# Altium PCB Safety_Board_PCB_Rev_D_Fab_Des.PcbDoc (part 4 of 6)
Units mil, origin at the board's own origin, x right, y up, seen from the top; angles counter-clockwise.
Board outline 11000 x 4400 mil, 6 copper layers (L1-TOP, L2-Plane, L3-Signal, L4-Signal, L5-Plane, L6-BOT); 712 components, 540 nets, 2214 pads, 875 vias.
Unrouted connection lines stored in the file: 3.
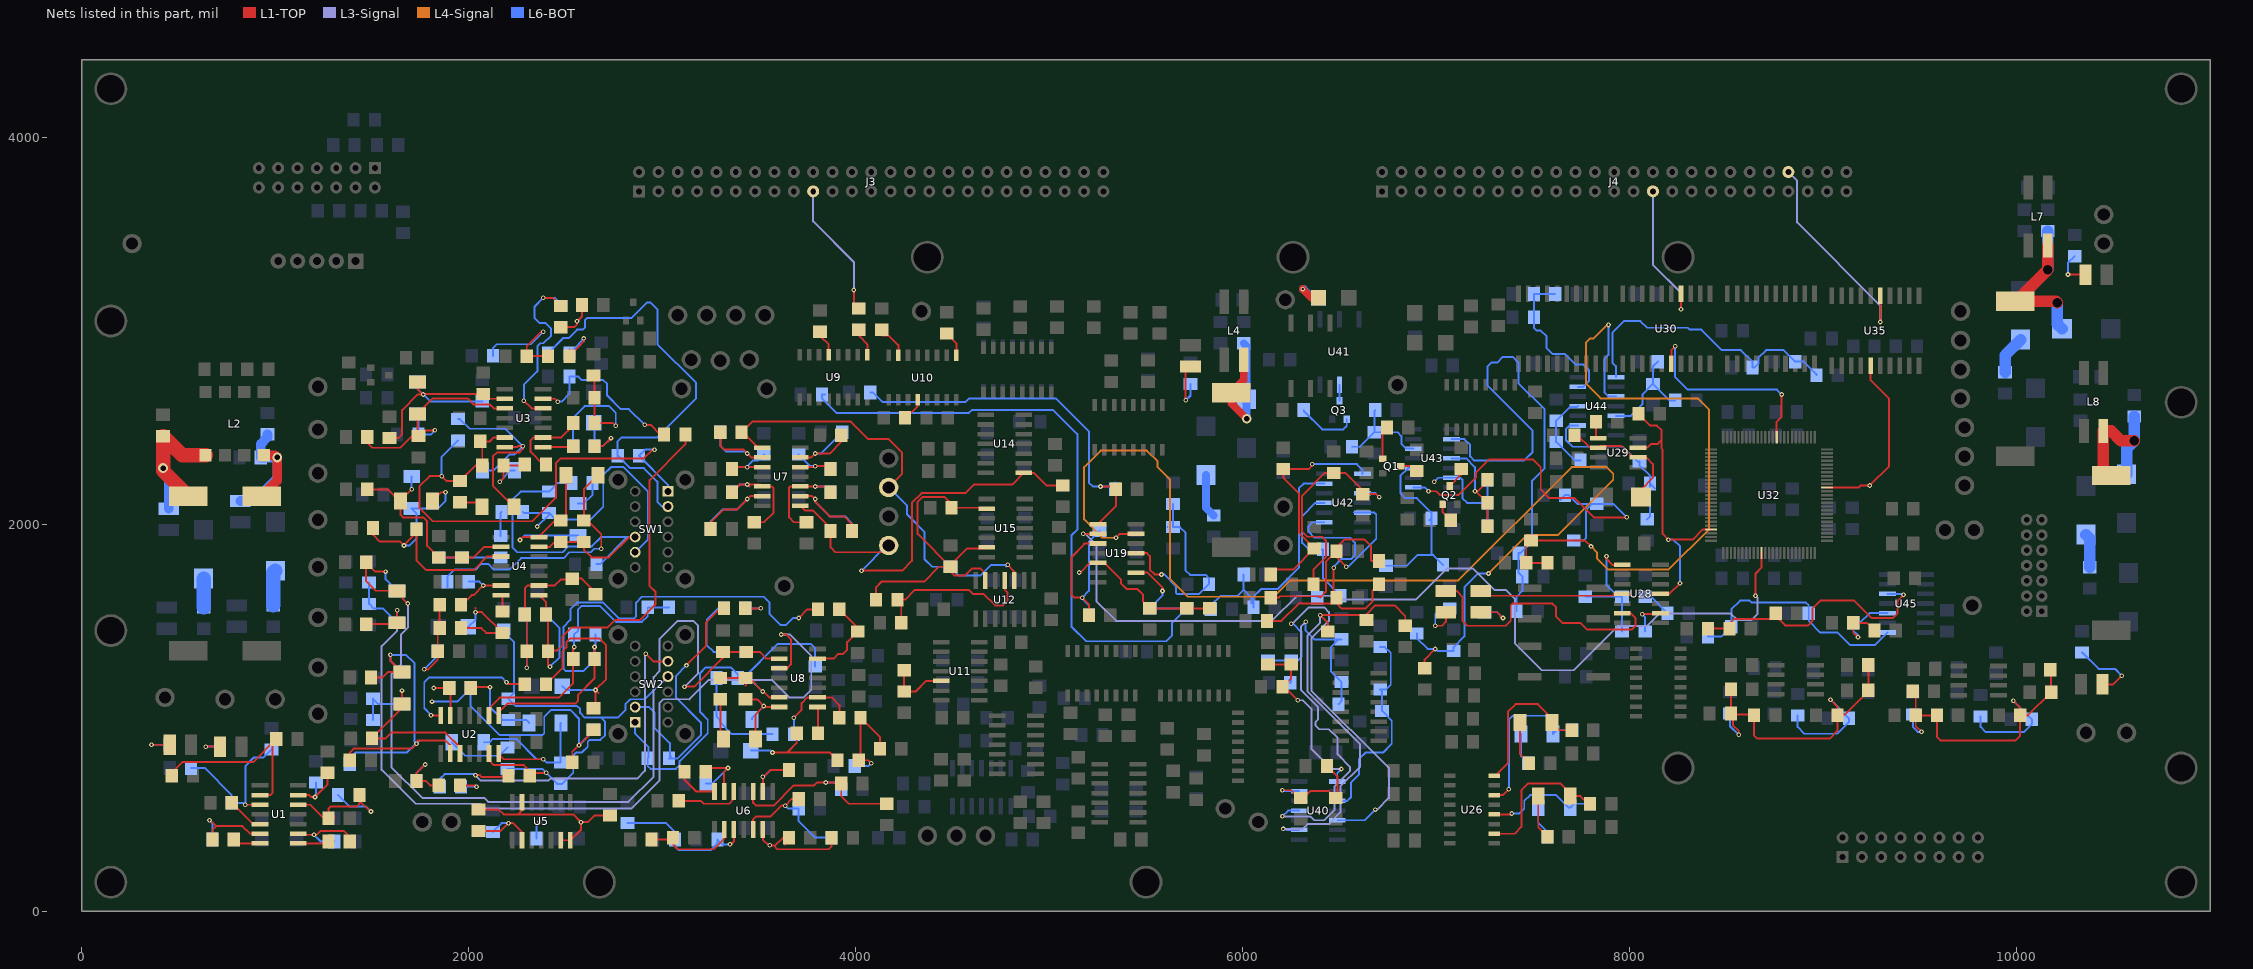
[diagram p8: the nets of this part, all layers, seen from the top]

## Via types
v1: diameter 24, hole 12, L1-TOP to L6-BOT, 720 vias
v2: diameter 50, hole 28, L1-TOP to L6-BOT, 138 vias
v3: diameter 28, hole 50, L1-TOP to L6-BOT, 17 vias

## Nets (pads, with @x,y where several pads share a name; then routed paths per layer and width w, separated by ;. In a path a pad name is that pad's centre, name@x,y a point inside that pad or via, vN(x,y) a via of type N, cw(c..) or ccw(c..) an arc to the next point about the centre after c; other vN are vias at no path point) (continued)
IBS: R53.2 R269.1 TP26.1 U7.1 U12.10 | length 2350.5
  L1-TOP w10: U7.1@3516.57,2395 3495,2395 3415,2475 R53.2@3410.12,2475 3465.12,2530 3975,2530 4065,2440 4170,2440 4240,2370 4240,2260 TP26.1@4170,2190 TP26.1@4205,2190 ; v1(4785,1790) 4820,1755 U12.10@4820,1708.43
  L6-BOT w10: TP26.1@4170,2190 4265,2095 4265,2050 4355,1960 4355,1820 4395.12,1779.88 R269.1@4490,1779.88 4490.12,1780 4490.12,1774.88 4530,1735 4645,1735 4700,1790 v1(4785,1790) 4775,1780
IBW: R69.2 R104.1 TP28.1 U7.8 U14.8 | length 2280.6
  L1-TOP w10: U7.8@3713.43,2095 3738.43,2070 3780,2070 3860,1990 R69.2@3860,1970 ; R69.2@3869.88,1965 3869.88,1880.12 3895,1855 4135,1855 TP28.1@4170,1890 TP28.1@4155,1890 ; v1(4030,1760) 4240,1760 4290,1810 4290,2110 4340,2160 4565,2160 4610,2205 4808.43,2205 U14.8@4868.43,2265 4920,2265 4984.88,2200.12 R104.1@5070,2200.12
  L6-BOT w10: v1(4030,1760) 4160,1890 TP28.1@4170,1890
"LAB SELECT LATCH": J4.44 U35.15 | length 1107.9
  L1-TOP w10: v1(9295,3045) U35.15@9295,3181.1
  L3-Signal w10: J4.44@8820,3820 8865,3775 8865,3560 9295,3130 v1(9295,3045)
LAB_SELECT_LATCH: U32.65 U35.5 | length 924.9
  L1-TOP w10: U32.65@9019.21,2189.37 9184.37,2189.37 9195,2200 v1(9240,2200) 9340,2300 9340,2649.04 9245,2744.04 U35.5@9245,2818.9
LOCAL_CLOCK: R169.2 U28.11 U29.3 U32.22 | length 1505.6
  L1-TOP w10: U29.3@8042.32,2395.04 8090.04,2395.04 8110,2415 8145,2415 8165,2435 ; R169.2@8044.88,2570 8105,2509.88 8140.12,2509.88 8165,2485 8165,2390 8170,2385 8170,1950 v1(8200,1920) 8325,1920 8377.83,1972.83 U32.22@8420.79,1972.83 ; U28.11@8158.43,1640 8205,1640 v1(8260,1695)
  L6-BOT w10: v1(8200,1920) 8225,1920 8260,1885 v1(8260,1695)
"MTR CNTR ERR": J3.19 R73.1 | length 702.2
  L1-TOP w10: v1(3990,3210) 3990,3140.12 R73.1@4015,3115.12
  L3-Signal w10: J3.19@3780,3720 3780,3565 3990,3355 v1(3990,3210)
"MTR CNTR ERR LATCH": J4.29 U30.14 | length 751.2
  L1-TOP w10: v1(8265,3110) U30.14@8265,3191.1
  L3-Signal w10: J4.29@8120,3720 8120,3340 8265,3195 v1(8265,3110)
MTR_CNTR_ERR_BUF: U19.2 U32.36 | length 4880.2
  L1-TOP w10: v1(5175,1950) U19.2@5251.57,1950 ; v1(8650,1630) 8650,1745 8680.63,1775.63 U32.36@8680.63,1850.79
  L3-Signal w10: v1(5175,1950) 5185,1950 5245,1890 5245,1600 5345,1500 6150.96,1500 6280.96,1630 6455,1630 6475,1610 6895,1610 7057,1772 7188,1772 7300,1660 7360,1660 7406,1614 7406,1384 7545,1245 7710,1245 7938,1473 8088,1473 8153,1538 8522,1538 8555,1505 8630,1505 8660,1535 8660,1620 v1(8650,1630)
MTR_CNTR_ERR_LATCH: U30.6 U32.86 | length 1078.1
  L1-TOP w10: U30.6@8215,2828.9 8215,2900 v1(8235,2920) ; U32.86@8759.37,2449.21 8759.37,2529.37 8785,2555 v1(8785,2670)
  L6-BOT w10: v1(8235,2920) 8235,2760 8300,2695 8760,2695 v1(8785,2670)
NetC4_2: C4.2 D5.A D18.K R15.2 R207.2 U2.2 | length 2090
  L1-TOP w10: C4.2@1361.89,753.11 C4.2@1389.53,753.11 ; C4.2@1384.88,780 1384.88,819.88 1405,840 1705,840 v1(1730,865) ; R15.2@1494.76,1208.11 1554.65,1208.11 1582.32,1235.79 D5.A@1662.32,1235.79 ; v1(1595,1325) 1595,1295.43 D5.A@1654.65,1235.79 ; v1@1734.65,874.65 1734.65,883.11 1879.65,883.11 1904.65,858.11 U2.2@1904.65,784.69
  L6-BOT w10: R207.2@1384.88,760 1384.88,789.88 1415,820 1680,820 1725,865 v1(1730,865) ; D18.K@1654.65,1235.79 1595,1295.43 v1(1595,1325) 1675,1325 1720,1280 1720,875 v1(1730,865) ; 1744.65,879.65 v1(1730,865)
NetC5_2: C5.2 R7.2 R208.2 U1.12 | length 784.1
  L1-TOP w10: U1.12@1118.43,550 1180,550 1250,480 R7.2@1274.88,480 1275,480.12 1275,530 1285,540 1420,540 1435.12,555.12 C5.2@1435.12,600 C5.2@1415.12,580 ; R7.2@1304.88,480 R7.2@1304.88,489.88 ; C5.2@1435.12,569.88 1495,510 v1(1495,515)
  L6-BOT w10: R208.2@1324.88,600 1384.88,540 1470,540 v1(1495,515)
NetC6_2: C6.2 D4.K D16.A R10.2 R204.2 U3.3 | length 1262.1
  L1-TOP w10: R10.2@1475.12,2450 1475.12,2419.88 1500,2395 1645,2395 1705.12,2455.12 C6.2@1740,2455.12 ; C6.2@1734.65,2468.23 C6.2@1739.76,2463.11 ; v1(1825,2485) 1769.88,2485 C6.2@1740,2455.12 ; U3.3@2186.22,2598.11 2129.65,2598.11 2109.65,2618.11 2026.89,2618.11 1995,2650 1814.21,2650 D4.K@1734.65,2570.43 1734.65,2460.47 C6.2@1740,2455.12
  L6-BOT w10: D16.A@1734.65,2570.43 1739.76,2565.32 R204.2@1739.76,2463.11 1803.11,2463.11 v1(1825,2485)
NetC7_2: C7.2 D2.K D17.A R12.2 R205.1 U4.3 | length 1523.5
  L1-TOP w10: R12.2@1505.12,1980 1505.12,1944.88 1540,1910 1645,1910 v1(1665,1890) C7.2@1729.76,1954.76 ; C7.2@1729.76,1973.11 1729.76,1812.99 1779.65,1763.11 2024.65,1763.11 2094.65,1833.11 U4.3@2166.22,1833.11 ; D2.K@1812.68,2120 1857.68,2165 v1(1880,2165)
  L6-BOT w10: v1(1665,1890) 1695,1890 1729.76,1924.76 1729.76,2055.32 D17.A@1704.65,2080.43 1840.43,2080.43 1880,2120 v1(1880,2165)
NetC8_2: C8.2 R25.1 R212.2 | length 374.3
  L1-TOP w10: C8.2@1759.76,643.11 C8.2@1729.76,673.11 ; v1(1774.65,758.11) 1729.76,713.23 C8.2@1729.76,673.11 ; R25.1@1844.88,650 1800,650 1776.89,673.11 C8.2@1729.76,673.11
  L6-BOT w10: R212.2@1729.76,673.11 1729.76,713.23 v1(1774.65,758.11)
NetC9_2: C9.2 D2.A D17.K R11.2 R26.2 U4.2 | length 1124.4
  L1-TOP w10: R11.2@1475.12,2180 1580,2180 D2.A@1643.66,2116.34 ; v1(1705,2180) 1647.32,2122.32 1647.32,2047.68 1660,2035 1765,2035 1784.65,2015.35 1784.65,1887.99 C9.2@1844.65,1827.99 R26.2@1964.65,1827.99 1964.76,1828.11 2024.65,1828.11 2079.65,1883.11 U4.2@2166.22,1883.11
  L6-BOT w10: D17.K@1704.65,2245.79 1705,2245.43 v1(1705,2180)
NetC11_2: C11.2 D4.A D16.K R9.2 R219.2 U3.2 | length 1250.5
  L1-TOP w10: R9.2@1590,2444.88 1634.88,2444.88 1655,2465 1655,2590 1734.65,2669.65 1764.65,2669.65 1767.99,2672.99 C11.2@2074.65,2672.99 2099.53,2648.11 U3.2@2186.22,2648.11 ; D4.A@1734.65,2735.79 1734.65,2700.35 v1(1765,2670)
  L6-BOT w10: D16.K@1734.65,2735.79 1734.65,2700.35 1800.12,2634.88 R219.2@2070,2634.88
NetC13_2: C13.2 R34.1 R218.2 | length 613
  L1-TOP w10: v1(2385,2995) 2375,2995 2299.76,2919.76 C13.2@2299.76,2868.11 R34.1@2409.53,2868.11
  L6-BOT w10: R218.2@2125.12,2870 2125.12,2910.12 2145,2930 2320,2930 v1(2385,2995)
NetC14_1: C14.1 C70.1 R31.1 R37.2 R44.1 U4.9 | length 1123.5
  L1-TOP w10: v1(2299.65,1258.11) 2299.53,1258.23 2299.53,1523.11 R31.1@2289.53,1533.11 2289.53,1667.99 2304.65,1683.11 2444.65,1683.11 2474.65,1713.11 2529.53,1713.11 R37.2@2534.65,1718.23 2584.53,1718.23 2654.65,1648.11 R44.1@2654.65,1637.99
  L6-BOT w10: C70.1@2289.53,1527.99 C70.1@2289.53,1533.11 2299.65,1522.99 v1(2299.65,1258.11)
NetC14_2: C14.2 C70.2 R31.2 R48.1 U4.8 | length 2355.2
  L1-TOP w10: U4.8@2363.07,1633.11 2399.76,1596.42 R31.2@2399.76,1533.11 2409.76,1523.11 2409.76,1272.99 v1(2419.65,1263.11) ; C14.2@2414.76,1348.11 2458.11,1348.11 2485,1375 2485,1420 2530,1465 2716.54,1465 2756.54,1505 2885,1505 2965,1585 2965,1650 2934.65,1680.35 2934.65,2228.11 3119.76,2413.23 R48.1@3119.76,2463.11
  L6-BOT w10: C70.2@2399.76,1533.11 2469.65,1463.23 2469.65,1313.11 v1(2419.65,1263.11)
NetC17_1: C17.1 R41.1 R228.2 R230.1 R232.1 SW1.10 U4.13 | length 2060.1
  L1-TOP w10: U4.13@2363.07,1883.11 2419.65,1883.11 C17.1@2444.53,1907.99 ; C17.1@2474.65,1907.99 R41.1@2594.65,1907.99 2594.65,1868.11 2634.65,1828.11 2724.65,1828.11 2830.28,1933.74 SW1.10@2860,1933.74
  L6-BOT w10: R232.1@2529.53,2213.11 2459.53,2213.11 R228.2@2414.65,2168.23 2268.23,2168.23 2225,2125 2225,1880 2250,1855 2485,1855 2515,1885 2635.96,1885 2684.7,1933.74 SW1.10@2860,1933.74 ; R230.1@2659.76,1793.11 2679.65,1793.11 2820.28,1933.74
NetC17_2: C17.2 D7.K D25.A U4.14 | length 808.9
  L1-TOP w10: v1(2264.65,1918.11) 2279.65,1933.11 U4.14@2363.07,1933.11 2363.07,1936.54 2444.76,2018.23 C17.2@2474.65,2018.23 2501.97,2045.55 D7.K@2501.97,2253.11
  L6-BOT w10: v1(2264.65,1918.11) 2286.97,1940.43 D25.A@2564.65,1940.43
NetC18_1: C18.1 C72.1 R233.1 R236.2 R240.1 U2.9 | length 1551.1
  L1-TOP w10: U2.9@2104.65,1011.54 2104.65,1048.11 2159.65,1103.11 2464.65,1103.11 2539.53,1177.99 2539.53,1359.53 v1(2545,1365)
  L6-BOT w10: R233.1@2539.53,1303.11 2539.53,1359.53 v1(2545,1365) 2544.88,1365.12 C72.1@2544.88,1430 2565,1450.12 2565,1560 2583,1578 2677,1578 2760,1495 2895,1495 2925.12,1525.12 R236.2@2925.12,1570 R240.1@3034.88,1570
NetC18_2: C18.2 C72.2 R66.1 R233.2 U2.8 | length 2948.9
  L1-TOP w10: U2.8@2154.65,1011.54 2154.65,1028.11 2199.65,1073.11 2549.65,1073.11 2564.65,1088.11 2564.65,1118.11 2649.76,1203.23 C18.2@2649.76,1303.11 2650,1303.35 v1(2650,1365) ; v1(3705,1515) 3750,1560 R66.1@3804.88,1560
  L6-BOT w10: R233.2@2649.76,1298.59 2593.08,1241.92 2500,1241.92 2488.46,1253.46 2488.46,1468.46 2525,1505 2525,1560 2560,1595 2695,1595 2778,1512 2852,1512 2865,1525 2865,1595 2895,1625 3525,1625 3555,1595 3555,1535 3610,1480 3640,1480 3675,1515 v1(3705,1515) ; R233.2@2649.76,1303.11 2649.76,1364.76 2655.12,1370.12 C72.2@2655.12,1430
NetC20_1: C20.1 R245.2 | length 159.8
  L1-TOP w10: C20.1@3428.54,1565 v1(3508.43,1565)
  L6-BOT w10: R245.2@3428.54,1565 v1(3508.43,1565)
NetC20_2: C20.2 R238.1 SW2.2 | length 1428.6
  L1-TOP w10: v1(3125,1270) 3225,1370 3225,1490 3300,1565 C20.2@3318.31,1565
  L6-BOT w10: SW2.2@2860,1055 2932.76,1055 2959.65,1028.11 2959.65,948.11 3039.76,867.99 R238.1@3039.76,794.65 ; R238.1@3045.12,800 R238.1@3035.12,790 3080,790 3200,910 3200,975 3070,1105 3070,1215 v1(3125,1270)
NetC21_1: C21.1 R52.1 R238.2 R242.1 R256.2 SW2.1 U8.6 | length 2284.8
  L1-TOP w10: R52.1@3300,1205.12 C21.1@3430,1205.12 3449.88,1205.12 v1(3520,1135) ; 3430,1165.12 3435,1170.12 ; v1@3523.43,1135 3553.43,1105 U8.6@3605,1105
  L6-BOT w10: SW2.1@2860,976.26 2860,917.76 2929.53,848.23 2929.53,794.65 R238.2@2924.88,790 2924.88,750.12 2940,735 3070,735 3090,755 3090,775 3235,920 3235,990 3195,1030 3195,1230 3225,1260 3355,1260 3390.12,1224.88 R242.1@3390.12,1205 3450,1205 v1(3520,1135) ; R242.1@3420,1205 3595,1380 3770,1380 3790,1360 R256.2@3790,1265.12
NetC21_2: C21.2 D9.K D27.A U8.7 | length 481.8
  L1-TOP w10: C21.2@3430,1094.88 3490.12,1094.88 3530,1055 U8.7@3605,1055 U8.7@3600.12,1059.88 ; D9.K@3482.68,890 3482.68,1017.68 v1(3525,1060)
  L6-BOT w10: D27.A@3462.68,990 3462.68,997.68 v1(3525,1060)
NetC22_2: C22.2 D3.A D15.K R13.2 R57.1 U8.2 | length 4888.4
  L1-TOP w10: v1(1570,1755) 1517.87,1755 R13.2@1469.76,1803.11 1469.76,1705.24 1519.21,1655.79 D3.A@1629.65,1655.79 1629.65,1645.35 v1(1685,1590) ; v1(3115,1160) 3165,1160 3313.43,1308.43 R57.1@3313.43,1339.88 3503.54,1339.88 3538.43,1305 U8.2@3605,1305
  L3-Signal w10: v1(1685,1590) 1685,1465 1650,1430 1650,1275 1600,1225 1600,745 1760,585 2080,585 2100,565 2825,565 2955,695 2955,1210 2985,1240 2985,1405 3080,1500 3160,1500 3185,1475 3185,1230 v1(3115,1160)
  L6-BOT w10: v1(1570,1755) 1570,1715 1629.21,1655.79 D15.K@1629.65,1655.79
NetC25_2: C25.2 R117.1 R123.1 U19.5 | length 825.2
  L1-TOP w10: v1(5155,1750) 5160,1750 5210,1800 5285,1800 5370,1715 5370,1695 5400,1665 5455,1665 5485,1635 5485,1600.12 R117.1@5520,1565.12 C25.2@5710,1565.12 R123.1@5830,1565.12
NetC26_2: C26.2 R127.1 R132.1 U40.1 | length 935.5
  L1-TOP w10: C26.2@6130,1274.88 R132.1@6250,1274.88 6250,1204.88 R127.1@6205.12,1160 6215,1160 v1(6285,1090) ; R132.1@6245,1289.88 R132.1@6250,1294.88
  L3-Signal w10: v1(6285,1090) 6310,1090 6355,1045 6355,840 6460,735 v1(6510,735)
  L6-BOT w10: U40.1@6488.43,670 6488.43,713.43 v1(6510,735)
NetC27_2: C27.2 R125.1 R129.1 U42.1 | length 1212.1
  L1-TOP w10: R125.1@6145.12,1740 6170.12,1765 6260.12,1765 C27.2@6370,1874.88 6320,1924.88 6320,1925 6290,1955 6290,2160 6210,2240 R129.1@6210,2284.88 6339.88,2284.88 6360,2305 v1(6360,2310)
  L6-BOT w10: v1(6360,2310) 6590,2310 6618.43,2281.57 U42.1@6618.43,2260
NetC28_2: C28.2 R130.1 R133.1 U40.13 | length 597.8
  L1-TOP w10: v1(6205,625) 6250,625 R130.1@6289.88,585.12 ; R130.1@6300,585.12 6315.12,585.12 6350,620 6445.12,620 R133.1@6480,585.12 6490,595.12 6490,695.12 C28.2@6435.12,750
  L6-BOT w10: v1(6205,625) 6205,630 6215,620 U40.13@6291.57,620
NetC29_2: C29.2 R131.1 R134.1 U42.3 | length 1184.4
  L1-TOP w10: R131.1@6365.12,1690 6365.12,1764.28 6430,1829.16 6430,1915 6410,1935 6334.04,1935 6307,1962.04 6307,2147 6424.88,2264.88 6530.12,2264.88 6620,2175 C29.2@6620,2155.12 6689.88,2155.12 v1(6705,2140)
  L6-BOT w10: U42.3@6618.43,2160 6685,2160 v1(6705,2140)
NetC30_2: C30.2 R126.1 R135.1 U42.5 | length 1446.8
  L1-TOP w10: R126.1@6145.12,1620 6185,1620 6192.66,1627.65 6407.66,1627.65 ; 6400,1620 6430,1650 6430,1805.12 R135.1@6484.88,1860 ; v1(6535,1780) 6484.88,1830.12 6484.88,1879.88 6525,1920 6630,1920 6662.43,1887.57 6662.43,1812.57 6665,1810 C30.2@6704.88,1810
  L6-BOT w10: v1(6535,1780) 6545,1780 6690,1925 6690,2050 6680,2060 6575,2060
NetC31_2: C31.2 R124.1 R136.1 U42.9 | length 1528.8
  L1-TOP w10: R124.1@6125.12,1500 6200,1500 6290,1590 6454.88,1590 R136.1@6484.88,1620 6470,1634.88 v1(6470,1775) ; R136.1@6470,1595 6485,1610 R136.1@6485,1645 ; R136.1@6484.88,1590.12 6510,1565 6635,1565 6670,1600 6670,1655.12 C31.2@6704.88,1690
  L6-BOT w10: U42.9@6421.57,2010 6360,2010 6340,1990 6340,1960 6370,1930 6555,1930 6580,1905 6580,1840 6560,1820 6510,1820 6470,1780 v1(6470,1775)
NetC32_2: C32.2 R137.1 R143.1 U40.9 | length 2301.1
  L1-TOP w10: R137.1@6440,1445.12 6440,1490 v1(6400,1530) 6615.12,1530 R143.1@6640,1505.12 6640,1535 6685,1580 6785,1580 6840,1525 C32.2@6840,1475.12
  L3-Signal w10: v1(6210,425) 6310,425 6335,450 6445,450 6505,510 6505,645 6605,745 6605,865 6335,1135 6335,1425 6400,1490 v1(6400,1530)
  L6-BOT w10: v1(6210,425) 6210,435 6225,420 U40.9@6291.57,420
NetC34_2: C34.2 R157.2 R158.1 U43.11 | length 555.6
  L1-TOP w10: v1(7200,2170) 7204.88,2170 C34.2@7264.88,2110 R158.1@7264.88,1990 ; 7215,2170 7264.88,2219.88 R157.2@7264.88,2230
  L6-BOT w10: U43.11@7078.43,2340 7155,2340 7200,2295 v1(7200,2170)
NetC35_2: C35.2 R156.1 R164.1 U44.3 | length 3423.3
  L1-TOP w10: R164.1@7574.88,1800 R156.1@7465.12,1800 7465.12,1890 C35.2@7490,1914.88 7770.12,1914.88 v1(7800,1885)
  L4-Signal w10: v1(7800,1885) 7830,1855 7830,1825 7890,1765 8200,1765 8410,1975 8410,2590.96 8350.96,2650 7850,2650 7775,2725 7775,2940 7795,2960 7813,2960 v1@7883,3030
  L3-Signal w10: v1@7890,3020 v1(7890,3030)
  L6-BOT w10: v1(7890,3030) 7890,2875 7870,2855 7870,2680 7890,2660 U44.3@7928.43,2660
NetC37_2: C37.2 U29.5 | length 93.4
  L1-TOP w10: C37.2@7824.88,2530 7824.88,2457.76 U29.5@7837.6,2445.04 U29.5@7839.84,2447.28
NetC38_1: C38.1 R162.1 U29.2 U29.6 | length 663
  L1-TOP w10: R162.1@7729.96,2460.04 7794.96,2395.04 U29.6@7837.6,2395.04 ; U29.6@7832.6,2390.04 7847.6,2405.04 7954.96,2405.04 8014.96,2345.04 8084.96,2345.04 8120,2310 8120,2240 8058.43,2178.43 C38.1@8058.43,2140
NetC40_2: C40.2 R170.1 R174.1 U45.5 | length 1404.1
  L1-TOP w10: C40.2@8405.12,1460 R170.1@8514.88,1460 8514.88,1484.88 8540,1510 8724.88,1510 R174.1@8754.88,1540 8754.88,1525.12 8803,1477 8922,1477 8945,1500 8945,1565 8985,1605 9160,1605 9250,1515 9360,1515 9385,1540 9385,1605 v1(9415,1635) v1@9415,1625
  L6-BOT w10: U45.5@9331.57,1640 9410,1640 v1(9415,1635)
NetC41_2: C41.2 C153.2 R171.2 R173.2 R175.2 R177.2 R178.2 R364.2 R369.1 | length 2065.8
  L1-TOP w10: R171.2@8522.85,1146.92 8522.85,1027.15 C41.2@8533.08,1016.92 ; v1(8562.96,911.92) 8562.96,931.92 8533.08,961.8 C41.2@8533.08,1016.92 ; v1(9037.96,1091.92) 9073.08,1056.8 9073.08,932.04 9032.96,891.92 8657.96,891.92 8642.85,907.04 8642.85,1016.92 C41.2@8533.08,1016.92 ; R175.2@9073.08,1016.92 9113.08,1016.92 9233.08,1136.92 R177.2@9233.08,1246.92
  L6-BOT w10: R364.2@8517.96,1021.8 8517.96,956.92 v1(8562.96,911.92) ; R369.1@8867.96,1011.8 8867.96,951.92 8902.96,916.92 9072.96,916.92 9133.08,977.04 C153.2@9133.08,996.92 9132.96,996.92 v1(9037.96,1091.92)
NetC42_2: C42.2 R176.1 R372.1 U45.3 | length 494.1
  L1-TOP w10: v1(9180,1415) 9155.12,1439.88 R176.1@9155.12,1490 9224.88,1490 C42.2@9264.88,1450
  L6-BOT w10: v1(9180,1415) 9180,1425 9155.12,1449.88 R372.1@9155.12,1490 9190,1490 9240,1540 U45.3@9331.57,1540
NetC43_2: C43.2 C160.2 R182.2 R184.2 R185.2 R186.2 R187.2 R378.2 R380.1 | length 2045.1
  L1-TOP w10: R182.2@9462.85,1136.92 9478.08,1121.68 9478.08,956.8 v1(9507.96,926.92) ; C43.2@9478.08,1011.92 R184.2@9587.85,1011.92 9587.85,902.04 9607.96,881.92 9992.96,881.92 10018.08,907.04 10018.08,1051.8 v1(9982.96,1086.92) ; R185.2@10018.08,1011.92 10058.08,1011.92 R187.2@10178.08,1131.92 10178.08,1241.92 R186.2@10173.08,1246.92
  L6-BOT w10: R378.2@9462.96,1016.8 9462.96,951.92 9487.96,926.92 v1(9507.96,926.92) ; R380.1@9812.96,1006.8 9812.96,951.92 9837.96,926.92 10037.96,926.92 10078.08,967.04 C160.2@10078.08,991.92 10077.96,991.92 v1(9982.96,1086.92)
NetC44_2: C44.2 L1.1 L2.1 R1.2 | length 846.7
  L1-TOP w75: L1.1@550,2145 420,2275 R1.2@420,2454.88 518.27,2356.61 L2.1@640,2356.61
  L6-BOT w50: v2(420,2290) 420,2275 450,2245 C44.2@450,2080.12
NetC46_2: C46.2 R190.1 | length 148.9
  L6-BOT w75: R190.1@630,1570.12 C46.2@630,1719.02
NetC47_2: C47.2 R189.2 R196.2 U1.3 | length 828.8
  L1-TOP w10: v1(845,550) U1.3@921.57,550
  L6-BOT w10: R189.2@565.12,740 635,740 775.12,599.88 C47.2@775.12,560 835,560 v1(845,550) 845,750 890,795 940.12,795 R196.2@980,834.88 R196.2@979.88,834.88
NetC48_2: C48.2 L2.4 L3.1 R193.2 R194.2 | length 888.9
  L1-TOP w50: L3.1@930,2145 1010,2225 v2(1010,2345) 998.39,2356.61 L2.4@940,2356.61
  L1-TOP w60: L3.1@930,2145 L3.1@940,2155
  L6-BOT w50: C48.2@820,2120.12 895.12,2120.12 1010,2235 v2(1010,2345) R193.2@925.12,2345 925.12,2415.12 960,2450 R194.2@960,2464.88
NetC50_1: C50.1 R195.1 | length 183
  L6-BOT w75: R195.1@990,1580.12 990,1749.02 C50.1@1000,1759.02
NetC61_2: C61.2 D3.K D15.A R14.2 R206.2 U8.3 | length 4962.2
  L1-TOP w10: R14.2@1469.76,1483.11 1622.32,1483.11 D3.K@1629.65,1490.43 1629.65,1554.65 v1(1630,1555) ; U8.3@3605,1255 3645,1255 3665,1275 3665,1405 3640,1430 v1(3615,1430)
  L3-Signal w7: 3005,1095 3140,1095
  L3-Signal w10: v1(1630,1555) 1630,1450 1550,1370 1550,730 1725,555 2060,555 2085,530 2840,530 2985,675 2985,1075 3005,1095 ; 3140,1095 3240,1195 3565,1195 3655,1105 3730,1105 3770,1145 3770,1320 3660,1430 v1(3615,1430)
  L6-BOT w10: R206.2@1484.65,1697.99 C61.2@1484.65,1588.23 1509.76,1563.11 1556.97,1563.11 D15.A@1629.65,1490.43 ; D15.A@1629.65,1474.65 D15.A@1629.65,1490.43 ; v1(1630,1555) 1630,1490.79 D15.A@1629.65,1490.43
NetC62_2: C62.2 D5.K D18.A R16.2 R209.1 U2.3 | length 1213.9
  L1-TOP w10: v1(1655,1140) 1654.65,1139.65 1654.65,1047.99 R16.2@1499.76,893.11 1569.65,893.11 1599.65,923.11 1879.65,923.11 1954.65,848.11 U2.3@1954.65,784.69
  L6-BOT w10: R209.1@1504.65,988.23 C62.2@1504.65,1097.99 1532.2,1070.43 D18.A@1654.65,1070.43 1655,1070.79 v1(1655,1140)
NetC63_1: C63.1 R25.2 | length 167.3
  L1-TOP w10: R25.2@1955.12,650 2032.76,650 v1(2039.65,643.11)
  L6-BOT w10: C63.1@1959.76,643.11 v1(2039.65,643.11)
NetC63_2: C63.2 R29.1 SW2.11 | length 2030.4
  L1-TOP w10: v1(2034.65,703.11) 2056.89,703.11 2067.59,692.41 2167.29,692.41 R29.1@2174.88,700 ; v1(2915,1330) 2953.78,1291.22 SW2.11@3029.29,1291.22
  L3-Signal w10: v1(2034.65,703.11) 2062.76,675 2411.66,675 2421.66,685 2870,685 2910,725 2910,1325 v1(2915,1330)
  L6-BOT w10: C63.2@1849.53,643.11 1849.53,682.99 1874.65,708.11 2029.65,708.11 v1(2034.65,703.11)
NetC64_1: C64.1 R19.2 R20.1 R21.1 R235.2 SW1.1 U3.6 | length 2824.6
  L1-TOP w10: U3.6@2186.22,2448.11 2129.65,2448.11 2109.65,2428.11 R19.2@2059.76,2428.11 2069.53,2418.35 R20.1@2069.53,2303.11 2034.53,2303.11 R21.1@1954.65,2223.23 1884.53,2223.23 v1(1859.65,2248.11) 1798.11,2248.11 1745,2195 1745,2085 1815,2015 2329.23,2015 2450,2135.77 2450,2315 2475,2340 2905,2340 2950,2385 v1(2960,2385)
  L6-BOT w10: v1(1859.65,2248.11) 1859.65,2347.99 C64.1@1944.65,2432.99 ; v1(2960,2385) 2911.65,2385 R235.2@2879.76,2353.11 3029.29,2203.58 SW1.1@3029.29,2169.96
NetC64_2: C64.2 D6.K D21.A U3.7 | length 1237.1
  L1-TOP w10: U3.7@2186.22,2398.11 2249.65,2398.11 2254.65,2403.11 v1(2279.65,2403.11) 2279.65,2389.65 2260,2370 2145,2370 2125,2350 2125,2197.68 D6.K@2232.68,2090
  L6-BOT w10: C64.2@1944.65,2543.23 1954.53,2543.23 2004.65,2493.11 2189.65,2493.11 v1(2279.65,2403.11) 2237.32,2360.79 2210.79,2360.79 2128.11,2278.11 D21.A@2071.97,2278.11
NetC65_1: C65.1 R222.2 | length 126.9
  L6-BOT w10: R222.2@2164.65,1938.23 2164.65,2058.23 C65.1@2169.53,2063.11
NetC65_2: C65.2 R228.1 SW1.11 | length 1357.9
  L6-BOT w10: C65.2@2279.76,2063.11 2284.88,2057.99 R228.1@2414.65,2057.99 ; v1(2354.65,1988.11) 2414.65,2048.11 R228.1@2414.65,2057.99 ; SW1.11@2860,1855 2925,1920 2925,2170 2800,2295 2735,2295 2695,2255 2695,2090 2630,2025 2447.64,2025 R228.1@2414.65,2057.99
NetC66_2: C66.2 R211.2 R222.1 | length 320
  L6-BOT w10: R211.2@1844.65,1827.99 R222.1@2164.65,1827.99
NetC69_1: C69.1 R34.2 | length 286.3
  L1-TOP w10: R34.2@2519.76,2903.23 R34.2@2519.76,2868.11 2570,2918.35 2570,2920 2595,2945 v1(2595,2960)
  L6-BOT w10: C69.1@2519.76,2903.23 C69.1@2519.76,2883.11 2570,2933.35 2570,2935 v1(2595,2960)
NetC69_2: C69.2 R235.1 SW1.2 | length 2271.7
  L6-BOT w10: C69.2@2409.53,2883.11 2489.53,2963.11 2518.11,2963.11 2560,3005 2590,3005 2600,3015 2600,3055 2610,3065 2840,3065 2920,3145 2940,3145 2975,3110 2975,2930 3175,2730 3175,2650 2973.11,2448.11 2789.65,2448.11 2769.53,2427.99 R235.1@2769.53,2338.23 ; R235.1@2769.53,2353.11 2771.89,2353.11 2835,2290 2905,2290 2975,2220 2975,2115 2998.78,2091.22 SW1.2@3029.29,2091.22
NetC73_1: C73.1 R29.2 R220.1 R223.1 R224.1 SW2.10 U2.6 | length 2563.3
  L1-TOP w10: U2.6@2104.65,814.69 2104.65,780.35 2130,755 2285,755 2315.12,724.88 R29.2@2315.12,700 2330.12,715 v1(2400,715)
  L6-BOT w7: 2835,1095 2910,1095
  L6-BOT w10: R220.1@2180,1454.88 2180,1445 2232.65,1392.35 2232.65,1126.23 R223.1@2204.65,1098.23 2242.87,1060 2560,1060 2575,1045 2575,1025 2600,1000 2770,1000 2810.85,1040.85 2810.85,1070.85 2835,1095 ; R224.1@2200,734.88 2380.12,734.88 2457.01,657.99 2482.99,657.99 2540,715 2540,805 2555,820 2585,820 2615,850 2615,875 2625,885 2680,885 2705,910 2705,980 2685,1000 ; 2910,1095 3027.48,1212.48 SW2.10@3029.29,1212.48
NetC73_2: C73.2 D20.A D23.K U2.7 | length 905.9
  L1-TOP w10: U2.7@2154.65,814.69 2154.65,810.35 2180,785 v1(2385,785)
  L6-BOT w10: D20.A@2077.32,873.11 2108.11,873.11 2125,890 2245,890 2350,785 v1(2385,785) 2401.77,768.23 C73.2@2474.65,768.23 2474.65,970.43 D23.K@2477.32,973.11
NetC78_2: C78.2 R237.2 R239.2 U6.3 | length 764.4
  L1-TOP w10: v1(3350,345) 3355,345 3370,360 U6.3@3370,421.57
  L6-BOT w10: R237.2@2820,454.88 3020.12,454.88 3065.12,409.88 3065.12,334.88 3085,315 3250,315 3285.12,350.12 C78.2@3285.12,370 3310.12,345 v1(3350,345)
NetC79_2: C79.2 R54.2 R247.2 U7.3 | length 359.4
  L1-TOP w10: R54.2@3360.12,2285 3370.12,2295 v1(3440,2295) U7.3@3516.57,2295
  L6-BOT w10: C79.2@3360.12,2285 3370.12,2295 v1(3440,2295) 3440,2300 3470,2330 3495.12,2330 R247.2@3525,2359.88
NetC80_2: C80.2 R55.2 R58.2 U7.5 | length 596
  L1-TOP w10: R55.2@3360.12,2165 3400.12,2205 3506.57,2205 U7.5@3516.57,2195 3565,2195 3575,2185 3575,2060 3525.12,2010.12 R58.2@3475,2010.12 ; v1(3440,2205) 3450,2195
  L6-BOT w10: C80.2@3360.12,2165 3400.12,2205 v1(3440,2205)
NetC82_2: C82.2 R245.1 R246.2 | length 461.1
  L6-BOT w10: R245.1@3318.31,1565 3290,1565 3230,1505 3230,1375 3265.12,1339.88 C82.2@3433.43,1339.88
NetC86_2: C86.2 R63.2 R252.2 U6.5 | length 678
  L1-TOP w10: U6.5@3470,421.57 3470,475 3485,490 3560,490 3615,545 v1(3635,545) 3670,580 R63.2@3704.88,580
  L6-BOT w10: v1(3635,545) 3650,530 C86.2@3704.88,530 3704.88,465.12 3790,380 R252.2@3874.88,380
NetC88_2: C88.2 R67.2 R248.2 U7.12 | length 360.6
  L1-TOP w10: U7.12@3713.43,2295 3785,2295 v1(3790,2300) 3850,2300 3865,2285 R67.2@3869.88,2285
  L6-BOT w10: R248.2@3705,2359.88 3764.88,2300 3854.88,2300 C88.2@3869.88,2285
NetC89_2: C89.2 R61.2 R68.2 U7.10 | length 577
  L1-TOP w10: R61.2@3745,2010.12 3679.88,2010.12 3655,2035 3655,2190 3660,2195 v1(3790,2195) 3839.88,2195 R68.2@3869.88,2165
  L6-BOT w10: v1(3790,2195) 3839.88,2195 C89.2@3869.88,2165
NetC90_2: C90.2 R76.2 R81.2 U6.10 | length 982.2
  L1-TOP w10: U6.10@3470,618.43 3470,560 3485,545 3575,545 3680,650 3785,650 3800,665 3919.88,665 R76.2@3924.88,660 3924.88,595.12 3964.88,555.12 R81.2@4160,555.12
  L6-BOT w10: v1(3845,665) 3889.88,665 C90.2@3924.88,630
NetC104_2: C104.2 R113.1 R261.1 U19.1 | length 1981.9
  L1-TOP w10: U19.1@5251.57,2000 5344.88,2093.31 R113.1@5344.88,2180 5329.88,2195 v1(5265,2195)
  L6-BOT w10: R261.1@4075.12,2680 4090,2680 4138,2632 4567.96,2632 4585.96,2650 5035,2650 5035,2649.04 5205,2479.04 5205,2215 5225,2195 5325,2195 C104.2@5340,2180 C104.2@5340,2215
NetC105_2: C105.2 R109.1 R287.1 U19.3 | length 1015.9
  L1-TOP w10: R109.1@5204.88,1530 5204.88,1585.12 v1(5170,1620) 5130,1620 5115,1635 5115,1830 5180,1895 5180,1900 U19.3@5251.57,1900
  L6-BOT w10: R287.1@5204.88,1530 5204.88,1580.12 5170,1615 v1(5170,1620) 5204.88,1654.88 5204.88,1909.88 C105.2@5260,1965
NetC108_2: C108.2 R298.1 R300.1 U19.11 | length 1104.9
  L1-TOP w10: U19.11@5448.43,1850 5505,1850 5520,1835 5520,1765 5545,1740 v1(5580,1740)
  L6-BOT w10: v1(5580,1740) 5595,1740 5655,1680 5655,1645 5660,1640 5775,1640 5825,1690 R300.1@5825.12,1690 5825.12,1719.88 5807.57,1737.43 5727.57,1737.43 5705,1760 5705,1955 5674.88,1985.12 C108.2@5640,1985.12 R298.1@5640,2104.88 ; C108.2@5610,1985 C108.2@5610,1985.12
NetC109_2: C109.2 R250.1 R295.1 U19.9 | length 3706.2
  L1-TOP w10: U19.9@5448.43,1750 5508,1750 5585,1673 v1(5585,1655)
  L6-BOT w10: R250.1@3840,2670 R250.1@3825.12,2670 3825.12,2649.88 3900,2575 4585,2575 4600,2590 5020,2590 5145,2465 5145,1971.66 5115,1941.66 5115,1470 5190,1395 5605,1395 5635,1425 5635,1490.12 C109.2@5710,1565.12 ; v1@5590,1650 v1(5585,1655) 5585,1630.12 R295.1@5520,1565.12 C109.2@5710,1565.12 ; C109.2@5710,1585 C109.2@5710,1565.12
NetC110_1: C110.1 R302.1 | length 225.5
  L6-BOT w40: C110.1@5810,2254.02 5810,2085.12 R302.1@5850,2045.12
NetC113_1: C113.1 L4.4 L5.1 R307.2 | length 761.2
  L1-TOP w40: L4.4@6005,2850 6005,2745 L5.1@5940,2680 5940,2625 v2(6020,2545)
  L6-BOT w40: R307.2@6005,2934.88 6020,2919.88 v2(6020,2545)
NetC114_2: C114.2 R303.1 R308.1 U42.13 | length 1293.8
  L6-BOT w10: R303.1@5834.88,1560 5834.88,1579.88 5885.12,1630.12 5974.88,1630.12 6004.88,1660.12 ; R308.1@6004.88,1740 6004.88,1660.12 ; C114.2@6045,1590 6045,1620 6004.88,1660.12 ; C114.2@6054.88,1570 6054.88,1624.88 6095,1665 6180,1665 6290,1775 6290,2185 6315,2210 U42.13@6421.57,2210
NetC115_2: C115.2 R309.1 R312.1 U40.5 | length 2228.7
  L3-Signal w10: v1(6250,1485) 6250,1480 6340,1570 6420,1570 6445,1545 6445,1500 6355,1410 6355,1140 6755,740 6755,585 6695,525 v1(6685,525)
  L6-BOT w10: C115.2@6130,1294.88 6284.88,1294.88 6305,1315 6305,1440 6260,1485 v1(6250,1485) ; R309.1@6245.12,1180 6250,1184.88 R312.1@6250,1294.88 ; 6300,1445 6305,1445 ; U40.5@6488.43,470 6630,470 v1(6685,525)
NetC117_2: C117.2 R314.1 R316.1 U42.11 | length 804.5
  L6-BOT w10: C117.2@6385.12,1620 6395.12,1630 R316.1@6504.88,1630 6414.88,1720 R314.1@6414.88,1870 6340,1870 6307,1903 6307,2042 6375,2110 U42.11@6421.57,2110
NetC119_2: C119.2 R313.1 R317.1 U40.11 | length 2189.9
  L3-Signal w10: v1(6205,490) 6350,490 6370,470 6420,470 6475,525 6475,645 6555,725 6555,745 6490,810 6490,895 6445,940 6395,940 6375,960 6375,977 6390,992 6390,1055 6300,1145 6300,1470 v1(6325,1495)
  L6-BOT w10: v1(6205,490) 6235,520 U40.11@6291.57,520 ; v1(6325,1495) 6325,1450 6370.12,1404.88 R317.1@6510,1404.88 ; R317.1@6494.88,1404.88 6455,1365 6455,1239.88 C119.2@6510,1184.88 6510,1084.88 R313.1@6495.12,1070
NetC121_2: C121.2 R315.1 R322.1 U43.5 | length 523.2
  L6-BOT w10: R315.1@6565.12,2400 6604.88,2400 R322.1@6680,2475.12 ; C121.2@6684.88,2590 6680,2585.12 R322.1@6680,2475.12 ; U43.5@6881.57,2390 6845,2390 6820,2415 6820,2455 6799.88,2475.12 R322.1@6680,2475.12
NetC122_2: C122.2 R324.1 R325.1 U40.3 | length 1097.1
  L6-BOT w10: U40.3@6488.43,570 6540,570 6560,590 6560,665 6601.87,706.87 6601.87,786.87 6635,820 6725,820 6770,865 6770,985 6720,1035 6720,1134.88 C122.2@6710,1144.88 6739.88,1144.88 6765,1170 6765,1335 6735.12,1364.88 R324.1@6710,1364.88
NetC124_2: C124.2 R323.1 R326.1 U43.3 | length 951.1
  L6-BOT w10: R323.1@6740,1785.12 6848,1785.12 6902.88,1840 6984.88,1840 ; U43.3@6881.57,2290 6855,2290 6815,2250 6815,2160 6840,2135 6900,2135 6975.12,2059.88 6975.12,1849.76 C124.2@7034.88,1790 ; R326.1@6965.12,2020 R326.1@6975.12,2030
NetC125_2: C125.2 R147.1 R328.1 U19.13 | length 6027.6
  L1-TOP w10: v1(5345,1930) 5365,1950 U19.13@5448.43,1950 ; R147.1@6940,1255.12 6940,1300 v1(6995,1355)
  L4-Signal w10: v1(5345,1930) 5275,1930 5180,2025 5180,2295 5265,2380 5505,2380 5560,2325 5560,2295 5623,2232 5623,1717 5715,1625 6160.96,1625 6245.96,1710 7115,1710 7700,2295 7880,2295 7915,2260 7915,2230 7630,1945 7470,1945 v1(7270,1745)
  L6-BOT w10: R328.1@6900,1434.88 6900,1410 6955,1355 v1(6995,1355) 7005.12,1344.88 C125.2@7090,1344.88 7090,1365 7145,1420 7145,1675 7215,1745 v1(7270,1745)
NetC126_2: C126.2 R339.2 R340.1 U43.13 | length 659.2
  L6-BOT w10: v1(6990,2220) 7010,2240 U43.13@7078.43,2240 ; U43.13@7105,2240 U43.13@7078.43,2240 ; R340.1@7264.88,1990 R339.2@7264.88,2230 ; C126.2@7264.88,2110 7160,2110 7135,2135 7135,2230 7125,2240 U43.13@7078.43,2240
NetC127_2: C127.2 R341.1 R342.1 U43.9 | length 2673
  L6-BOT w10: U43.9@7078.43,2440 7145,2440 7175,2410 7175,2350 7195,2330 7455,2330 7498,2373 7498,2482.96 7265,2715.96 7265,2815 7285,2835 7315,2835 7345,2865 7395,2865 7425,2835 7425,2729.04 7560,2594.04 7560,2290 7495,2225 7495,1909.88 7435.12,1850 R341.1@7425.12,1850 7425.12,1749.76 R342.1@7444.88,1730 7444.88,1654.88 7414.88,1624.88 C127.2@7414.88,1550
NetC129_2: C129.2 R337.1 R338.1 U44.13 | length 821.9
  L6-BOT w10: C129.2@7614.88,3190 R337.1@7505.12,3190 7505.04,3070 7505,3015 7520,3000 7540,3000 7570,2970 7570,2910 7600,2880 7665,2880 7720,2825 7760,2825 7790,2795 7790,2740 7760,2710 U44.13@7731.57,2710
NetC130_2: C130.2 R347.1 R354.1 U43.1 | length 2065
  L1-TOP w10: v1(6960,2170) 7000,2170 7020,2150 7115,2150 7205,2240 7205,2265 7275,2335 7500,2335 7540,2295 7540,2180 7585,2135 7715,2135 7815,2035 v1(7985,2035)
  L6-BOT w10: U43.1@6881.57,2190 6940,2190 v1(6960,2170) ; C130.2@7640,2124.88 C130.2@7665.12,2150 7685,2150 7729.88,2105.12 7914.88,2105.12 v1(7985,2035) ; R347.1@7709.88,1915 R347.1@7710,1914.88 7759.88,1914.88 7775,1930 7775,2075 R354.1@7805.12,2105.12
NetC131_2: C131.2 R355.1 R356.1 U28.1 | length 713.8
  L1-TOP w10: v1(7880,1835) 7880,1820 7910,1790 U28.1@7961.57,1790
  L6-BOT w10: C131.2@7770,1624.88 R355.1@7960,1624.88 R356.1@7960,1445.12 ; v1(7880,1835) 7880,1685 R355.1@7940.12,1624.88
NetC132_2: C132.2 R345.1 R346.1 U44.11 | length 416.7
  L6-BOT w10: U44.11@7731.57,2610 7726.46,2604.88 7690,2604.88 R345.1@7620,2534.88 R346.1@7620,2425.12 7715.12,2330 C132.2@7744.88,2330
NetC133_2: C133.2 R357.1 R358.1 U44.9 | length 914.5
  L6-BOT w10: U44.9@7731.57,2510 7690,2510 7670,2490 7670,2435 7705,2400 7965,2400 8040.12,2324.88 R357.1@8050,2324.88 8050,2305 8105.12,2249.88 8105.12,2040.24 R358.1@8090,2025.12 ; C133.2@8105.12,2210 C133.2@8130,2185.12
NetC135_2: C135.2 R359.1 R360.1 U44.5 | length 565.3
  L6-BOT w10: U44.5@7928.43,2560 8005.96,2560 8065,2619.04 8065,2670.12 R360.1@8120,2725.12 ; R359.1@8145.12,2840 8120,2814.88 R360.1@8120,2725.12 ; C135.2@8234.88,2640 8205.12,2640 R360.1@8120,2725.12
NetC136_2: C136.2 R361.1 R362.1 U28.9 | length 473.6
  L1-TOP w10: v1(8065,1535) 8153.43,1535 U28.9@8158.43,1540
  L6-BOT w10: R362.1@8080,1445.12 8080,1520 v1(8065,1535) 8189.88,1535 C136.2@8194.88,1540 8110,1624.88 R361.1@8080,1624.88
NetC141_2: C141.2 R365.1 R368.1 U45.1 | length 1224.8
  L6-BOT w10: C141.2@8405.12,1420 8474.88,1420 R365.1@8524.88,1470 8524.88,1559.88 8570,1605 8620,1605 8630,1595 8910,1595 8925.12,1579.88 8925.12,1499.88 8985,1440 9075,1440 9140,1375 9266.57,1375 U45.1@9331.57,1440
NetC144_2: C144.2 R367.1 R371.1 U44.1 | length 1546
  L6-BOT w10: U44.1@7928.43,2760 7928.43,2816.57 7910,2835 7910,2990 7970,3050 8055,3050 8090,3015 8300,3015 8310,3005 8370,3005 8475,2900 8575,2900 8635.12,2839.88 C144.2@8635.12,2810 8645,2810 8665,2830 8665,2860 8705,2900 8795.12,2900 R367.1@8855.12,2840 8900,2840 8964.88,2775.12 R371.1@8964.88,2770
NetC157_1: C157.1 R382.1 | length 202
  L6-BOT w60: R382.1@9940,2785.12 9940,2874.02 C157.1@10020,2954.02
NetC161_1: C161.1 L6.1 L7.4 R386.2 | length 920.4
  L1-TOP w60: L6.1@9992.96,3151.92 10203.08,3151.92 v3(10210,3145) ; L6.1@9996.92,3151.92 v3(10160,3315) L7.4@10160,3440
  L6-BOT w60: v3(10160,3315) R386.2@10160,3514.88 ; v3(10210,3145) 10210,3034.02 C161.1@10234.02,3010
NetC163_1: C163.1 R389.1 | length 177.2
  L6-BOT w60: C163.1@10357.96,1945.93 10377.96,1925.93 R389.1@10377.96,1777.04
NetC164_1: C164.1 L8.4 L9.1 R391.2 | length 742.7
  L1-TOP w60: L9.1@10487.96,2251.92 10447.96,2291.92 L8.4@10447.96,2481.92 10487.96,2481.92 10537.96,2431.92 v3(10607.96,2431.92)
  L6-BOT w60: C164.1@10567.96,2257.9 10567.96,2391.92 v3(10607.96,2431.92) R391.2@10607.96,2556.8
NetD6_A: D6.A R21.2 | length 122.2
  L1-TOP w10: R21.2@1954.65,2112.99 2044.33,2112.99 D6.A@2067.32,2090
NetD7_A: D7.A R41.2 R214.1 | length 1394.8
  L1-TOP w10: D7.A@2667.32,2253.11 2594.65,2180.43 R41.2@2594.65,2018.23 2614.53,2018.23 2684.65,1948.11 v1(2684.65,1873.11)
  L6-BOT w10: R214.1@1889.53,1673.23 1889.53,1729.53 1925,1765 2035,1765 2065,1795 2100,1795 2130,1765 2210,1765 2270,1825 2490,1825 2520,1855 2630,1855 2648.11,1873.11 v1(2684.65,1873.11)
NetD9_A: D9.A R52.2 | length 212.1
  L1-TOP w10: R52.2@3300,1094.88 3300,907.32 D9.A@3317.32,890
NetD10_K: D10.K D28.A | length 200.3
  L1-TOP w40: v1(6310,3215) 6355,3170 D10.K@6391.5,3170
  L6-BOT w40: v1(6310,3215) 6315,3215 6360,3170 D28.A@6391.5,3170
NetD13_A: D13.A R165.2 U26.8 | length 777.2
  L1-TOP w10: U26.8@7300.16,700 7305,700 7370,765 7370,1030 7410,1070 7525,1070 7597.68,997.32 D13.A@7597.68,975 7637.68,935 R165.2@7699.88,935
NetD13_K: D13.K R159.1 | length 229.7
  L1-TOP w10: D13.K@7432.32,975 7432.32,812.68 7479.88,765.12 R159.1@7479.88,765
NetD14_A: D14.A R167.2 U26.2 | length 764.4
  L1-TOP w10: U26.2@7300.16,400 7405,400 7440,435 7440,625 7475,660 7640,660 7692.68,607.32 D14.A@7692.68,595 7745,595 7785,555 R167.2@7794.88,555
NetD14_K: D14.K R160.1 | length 229.7
  L1-TOP w10: D14.K@7527.32,595 7527.32,432.56 R160.1@7574.88,385
NetD19_K: D19.K R22.2 R28.2 | length 504.4
  L1-TOP w10: R22.2@1959.76,1463.11 2064.65,1463.11 2089.76,1437.99 R28.2@2174.65,1437.99 2067.64,1545 v1(2035,1545) ; 2034.65,1563.11 2034.65,1568.11
  L6-BOT w10: D19.K@1998.5,1470 2035,1506.5 v1(2035,1545)
NetD20_K: D20.K R224.2 | length 334.4
  L6-BOT w10: D20.K@1911.97,873.11 1981.97,803.11 2157.99,803.11 R224.2@2200,845.12
NetD21_K: D21.K R20.2 R30.1 | length 304.5
  L1-TOP w10: v1(2160,2220) 2179.76,2239.76 R20.2@2179.76,2303.11 2284.53,2303.11 R30.1@2289.53,2308.11
  L6-BOT w10: v1(2160,2220) 2218.11,2278.11 D21.K@2237.32,2278.11
NetD22_K: D22.K R32.2 R42.2 | length 1052.8
  L1-TOP w10: R32.2@2399.76,1173.11 2484.65,1257.99 2484.65,1343.11 2505,1363.46 2505,1390 2525,1410 2675,1410 2709.65,1375.35 2709.65,1198.11 v1(2654.65,1143.11) ; R42.2@2644.65,1048.23 2654.65,1058.23 v1(2654.65,1143.11) ; v1@2654.65,1153.11 v1(2654.65,1143.11) ; 2669.65,1128.11 v1(2654.65,1143.11)
  L6-BOT w10: D22.K@2483.15,1163.11 2503.15,1143.11 v1(2654.65,1143.11)
NetD23_A: D23.A R24.1 R223.2 | length 442.4
  L1-TOP w10: R24.1@2009.76,1153.11 2014.76,1158.11 v1(2109.65,1158.11)
  L6-BOT w10: v1(2109.65,1158.11) 2109.65,1053.11 2174.76,987.99 2297.09,987.99 D23.A@2311.97,973.11
NetD24_K: D24.K R40.2 R229.2 | length 328.8
  L1-TOP w10: R40.2@2649.76,2403.11 2693.11,2403.11 v1(2735,2445)
  L6-BOT w10: D24.K@2644.65,2524.61 2649.76,2519.49 R229.2@2649.76,2403.11 2693.11,2403.11 v1(2735,2445)
NetD25_K: D25.K R232.2 | length 154.7
  L6-BOT w10: D25.K@2564.65,2105.79 2592.32,2105.79 2639.76,2153.23 R232.2@2639.76,2213.11
NetD26_K: D26.K R62.2 R71.2 | length 587.9
  L1-TOP w10: v1(3570,820) 3864.88,820 R71.2@3904.88,780 ; 3644.76,820 3694.88,870.12 R62.2@3694.88,920
  L6-BOT w10: D26.K@3458.5,830 3560,830 v1(3570,820)
NetD27_K: D27.K R242.2 R249.1 | length 533.1
  L6-BOT w10: R242.2@3279.88,1205 3279.88,1007.44 D27.K@3297.32,990 3297.32,977.68 3360,915 R249.1@3569.88,915
NetD29_A: D29.A R350.2 U26.6 | length 869.6
  L1-TOP w10: U26.6@7300.16,600 7345,600 v1(7375,630)
  L6-BOT w10: v1(7375,630) 7375,990 7395,1010 7570,1010 7602.68,977.32 D29.A@7602.68,915 7622.68,935 R350.2@7704.88,935
NetD29_K: D29.K R343.1 | length 165.6
  L6-BOT w10: D29.K@7437.32,915 7437.32,802.56 R343.1@7474.88,765
NetD30_A: D30.A R352.2 U26.4 | length 594.8
  L1-TOP w10: U26.4@7300.16,500 7385,500 v1(7390,505)
  L6-BOT w10: v1(7390,505) 7430,505 7455,530 7455,570 7485,600 7620,600 7685,535 D30.A@7692.68,535 7712.68,555 R352.2@7794.88,555
NetD30_K: D30.K R344.1 | length 169.7
  L6-BOT w10: D30.K@7527.32,535 7527.32,457.68 7574.88,410.12 R344.1@7574.88,385
NetDS1_A: DS1.A R188.2 | length 189.8
  L1-TOP w10: v1(360,860) DS1.A@454.88,860
  L6-BOT w10: v1(360,860) R188.2@454.88,860
NetDS2_K: DS2.K R191.2 | length 149.8
  L1-TOP w10: v1(640,850) DS2.K@714.88,850
  L6-BOT w10: v1(640,850) R191.2@714.88,850
NetDS3_K: DS3.K R301.2 | length 285.5
  L1-TOP w10: v1(5705,2640) 5705,2789.88 DS3.K@5730,2814.88
  L6-BOT w10: v1(5705,2640) 5730,2665 R301.2@5730,2724.88 ; v1@5705,2650 5705,2655
NetDS4_A: DS4.A R334.1 | length 260.5
  L1-TOP w10: v1(6995,1475) 7030,1475 7050,1495 DS4.A@7050,1544.88
  L6-BOT w10: v1(6995,1475) 6995,1535 7024.88,1564.88 R334.1@7070,1564.88
NetDS4_K: DS4.K U28.6 | length 1433.6
  L1-TOP w10: DS4.K@7050,1655.12 7104.88,1655.12 7135,1625 7135,1500 7160,1475 7360,1475 7385,1500 7385,1580 7395,1590 7600,1590 7620,1570 7620,1521.66 7651.66,1490 7745,1490 7780,1455 8010,1455 8030,1475 8030,1515 8005,1540 U28.6@7961.57,1540
NetDS5_A: DS5.A R336.1 | length 234.8
  L1-TOP w10: DS5.A@7230,1544.88 7315.12,1544.88 v1(7345,1515)
  L6-BOT w10: R336.1@7250,1544.88 7315.12,1544.88 v1(7345,1515)
NetDS5_K: DS5.K U28.4 | length 746.1
  L1-TOP w10: DS5.K@7230,1655.12 7255.12,1630 7910,1630 7920,1640 U28.4@7961.57,1640
NetDS6_K: DS6.K R387.2 | length 199.3
  L1-TOP w10: v1(10265,3290) DS6.K@10354.88,3290
  L6-BOT w10: v1(10265,3290) 10265,3349.88 R387.2@10300,3384.88
NetDS7_K: DS7.K R390.2 | length 373.2
  L1-TOP w10: DS7.K@10443.08,1171.92 10497.96,1171.92 v1(10542.96,1216.92)
  L6-BOT w10: R390.2@10337.96,1336.8 10422.85,1251.92 10507.96,1251.92 v1(10542.96,1216.92)
NetQ1_1: Q1.1 R144.1 | length 171.8
  L1-TOP w10: Q1.1@6722.76,2337.4 6722.76,2477.87 R144.1@6744.88,2500
NetQ1_3: Q1.3 R145.2 | length 93.2
  L1-TOP w10: Q1.3@6817.24,2300 6874.88,2300 R145.2@6900,2274.88
NetQ2_1: Q2.1 R150.1 | length 100.4
  L1-TOP w10: Q2.1@7032.6,2102.76 7032.6,2062.4 7075,2020 R150.1@7075.12,2020
NetQ2_3: Q2.3 R152.2 | length 114.9
  L1-TOP w10: Q2.3@7070,2197.24 7130,2257.24 R152.2@7130,2284.88 ; R152.2@7147.64,2274.88 R152.2@7150,2274.88
NetQ3_1: Q3.1 R311.1 | length 309.3
  L6-BOT w10: R311.1@6315.12,2590 6315.12,2584.88 6410,2490 6520,2490 6537.4,2507.4 Q3.1@6537.4,2542.76
NetQ3_3: Q3.3 U41.2 | length 83.5
  L6-BOT w10: Q3.3@6500,2637.24 U41.2@6500,2720.71
NetR2_1: R2.1 R5.2 U1.2 | length 955.1
  L1-TOP w10: R2.1@464.88,700 464.88,714.88 520,770 884.88,770 R5.2@1004.88,890 ; U1.2@921.57,600 975,600 985,610 R5.2@985,870.12
NetR3_2: R3.2 U1.5 | length 192
  L1-TOP w10: R3.2@775.12,560 885.12,450 U1.5@921.57,450
NetR4_1: R4.1 R192.2 U1.6 | length 475.1
  L1-TOP w10: v1(660,470) 665,470 695,440 ; R4.1@674.88,370 674.88,419.88 695,440 ; U1.6@921.57,400 870,400 830,440 695,440
  L6-BOT w10: v1(660,470) 674.88,455.12 R192.2@674.88,370
NetR4_2: R4.2 U1.7 | length 144.7
  L1-TOP w10: R4.2@785.12,370 805.12,350 U1.7@921.57,350
NetR6_1: R6.1 R199.2 U1.13 | length 319.5
  L1-TOP w10: U1.13@1118.43,600 1175,600 1185,590 v1(1205,590) 1270,655 R6.1@1270,714.88
  L6-BOT w10: v1(1205,590) 1210,595 R199.2@1210,664.88
NetR8_1: R8.1 R201.2 U1.9 | length 433.8
  L1-TOP w10: U1.9@1118.43,400 1123.43,395 1215,395 1235,415 1355,415 1385.12,384.88 R8.1@1385.12,360
  L6-BOT w10: v1(1200,395) 1235,360 R201.2@1304.88,360
NetR8_2: R8.2 U1.8 | length 160.6
  L1-TOP w10: U1.8@1118.43,350 1264.88,350 R8.2@1274.88,360
NetR18_1: R18.1 R214.2 U4.6 | length 331
  L1-TOP w10: R18.1@1959.76,1583.11 1964.65,1583.11 2014.65,1633.11 2024.65,1633.11 v1(2074.65,1683.11) U4.6@2166.22,1683.11
  L6-BOT w10: R214.2@1999.76,1703.11 2054.65,1703.11 v1(2074.65,1683.11)
NetR18_2: R18.2 R22.1 R23.2 R215.1 | length 499.7
  L1-TOP w10: v1(1770,1250) 1790,1250 1839.53,1299.53 1839.53,1453.11 R22.1@1849.53,1463.11 R18.2@1849.53,1583.11
  L6-BOT w10: v1(1770,1250) 1839.53,1319.53 R215.1@1839.53,1343.11
NetR24_2: R24.2 R216.1 U2.13 | length 310.7
  L1-TOP w10: v1(1819.65,1153.11) R24.2@1899.53,1153.11 ; U2.13@1904.65,1011.54 R24.2@1904.65,1147.99 ; R24.2@1899.53,1153.11 R24.2@1904.65,1147.99 ; R24.2@1899.53,1153.11 R24.2@1904.65,1147.99
  L6-BOT w10: v1(1819.65,1153.11) R216.1@1899.53,1153.11
NetR27_1: R27.1 R221.2 U5.9 | length 402.4
  L1-TOP w10: R27.1@2050,414.88 2164.88,414.88 v1(2205,455) 2230,455 2275,410 U5.9@2275,366.57
  L6-BOT w10: R221.2@2125,409.88 2170.12,455 v1(2205,455)
NetR27_2: R27.2 R47.1 R217.2 U5.6 U5.13 U5.14 | length 1090.5
  L1-TOP w10: R27.2@2050,525.12 2154.88,525.12 2180,500 2540,500 v1(2580,460) ; 2255,500 2275,520 U5.6@2275,563.43 ; v1(2365,460) 2365,500 ; U5.13@2475,366.57 U5.14@2525,366.57 2580,421.57 v1(2580,460) ; R47.1@2730,494.88 2649.88,494.88 2615,460 v1(2580,460)
  L6-BOT w10: R217.2@2350.12,375 2350.12,445.12 v1(2365,460)
NetR28_1: R28.1 U4.7 | length 88.4
  L1-TOP w10: U4.7@2166.22,1633.11 2174.65,1624.69 R28.1@2174.65,1548.23
NetR30_2: R30.2 R39.1 U3.9 | length 446.3
  L1-TOP w10: U3.9@2373.07,2438.11 U3.9@2383.07,2448.11 ; R30.2@2399.76,2308.11 2384.65,2308.11 2319.65,2373.11 2319.65,2433.11 2334.65,2448.11 2478.11,2448.11 2539.53,2509.53 R39.1@2539.53,2523.11
NetR32_1: R32.1 U2.14 | length 779.6
  L1-TOP w10: v1(1804.65,1013.11) 1806.22,1011.54 U2.14@1854.65,1011.54 ; v1(2194.65,1183.11) 2204.65,1173.11 R32.1@2289.53,1173.11
  L6-BOT w10: v1(1804.65,1013.11) 1804.65,1015.35 1770,1050 1770,1183.46 1794.65,1208.11 2169.65,1208.11 v1(2194.65,1183.11)
NetR33_1: R33.1 R35.1 R231.2 | length 303.6
  L1-TOP w10: R33.1@2479.41,3013.23 R33.1@2474.65,3017.99 2544.53,3017.99 2559.65,3033.11 v1(2559.65,3048.11) 2584.53,3072.99 R35.1@2584.53,3133.11
  L6-BOT w10: v1(2559.65,3048.11) 2584.53,3072.99 R231.2@2584.53,3133.11
NetR33_2: R33.2 R227.2 U3.12 | length 1006.8
  L1-TOP w10: v1(2284.65,2638.11) 2324.65,2598.11 U3.12@2383.07,2598.11 ; v1(2385,3170) 2432.87,3170 R33.2@2474.65,3128.23
  L6-BOT w10: v1(2284.65,2638.11) 2284.65,2719.65 2355,2790 2355,2920 2370,2935 2385,2935 2425,2975 2425,3010.96 2395.96,3040 2365,3040 2340,3065 2340,3125 v1(2385,3170) 2445,3170 2474.65,3140.35 R227.2@2474.65,3128.23
NetR36_1: R36.1 R38.2 R39.2 R229.1 | length 836.8
  L1-TOP w10: R36.1@2644.65,2767.99 2649.76,2762.87 R38.2@2649.76,2653.11 R39.2@2649.76,2523.11 2744.65,2523.11 v1(2759.65,2508.11)
  L6-BOT w10: R229.1@2539.53,2403.11 2539.53,2550.49 2599.04,2610 2725,2610 2759.65,2575.35 v1(2759.65,2508.11)
NetR40_1: R40.1 U3.8 | length 158.5
  L1-TOP w10: U3.8@2383.07,2398.11 2534.53,2398.11 R40.1@2539.53,2403.11
NetR42_1: R42.1 R43.1 R216.2 R234.2 | length 1528
  L1-TOP w10: R43.1@2534.88,770 2534.88,823.35 2644.65,933.11 R42.1@2644.65,937.99 ; R42.1@2669.53,937.87 R42.1@2669.65,937.99
  L6-BOT w10: v1(1809.65,1083.11) 1939.76,1083.11 R216.2@2009.76,1153.11 2009.76,1060.24 2160,910 2380,910 2390,920 2390,1005 2425,1040 2525,1040 2569.65,995.35 v1(2569.65,858.11) 2644.65,933.11 R234.2@2644.65,937.99
NetR45_2: R45.2 R51.1 U6.2 | length 493.7
  L1-TOP w10: R45.2@2945.12,370 3044.88,370 R51.1@3054.88,380 3054.88,345.12 3080,320 3265,320 3320,375 U6.2@3320,421.57
NetR48_2: R48.2 R226.1 U3.13 | length 901.3
  L1-TOP w10: U3.13@2383.07,2648.11 2444.65,2648.11 v1(2459.65,2633.11) ; v1(2909.65,2513.11) 2939.65,2513.11 2989.65,2463.11 R48.2@3009.53,2463.11
  L6-BOT w10: v1@2459.65,2630.35 v1(2459.65,2633.11) 2479.65,2633.11 2519.76,2673.23 R226.1@2519.76,2763.11 2566.89,2763.11 2585,2745 2695,2745 2715,2725 2715,2665 2785,2595 2827.76,2595 v1(2909.65,2513.11)
NetR49_2: R49.2 U6.12 | length 339.9
  L1-TOP w10: R49.2@3085.12,570 3200,570 3215,555 3345,555 3370,580 U6.12@3370,618.43
NetR50_1: R50.1 R241.2 U6.13 | length 401
  L1-TOP w10: R50.1@3225.12,720 3245.12,740 v1(3340,740) 3320,720 U6.13@3320,618.43
  L6-BOT w10: R241.2@3225.12,660 3260,660 v1(3340,740)
NetR50_2: R50.2 U6.14 | length 220.6
  L1-TOP w10: R50.2@3114.88,720 3114.88,680.12 3176.57,618.43 U6.14@3270,618.43
NetR53_1: R53.1 R243.2 U7.2 | length 538.1
  L1-TOP w10: R53.1@3299.88,2475 3299.88,2405.12 3320,2385 3420,2385 3460,2345 U7.2@3516.57,2345
  L6-BOT w10: R243.2@3299.88,2475 3299.88,2405.12 3330,2375 3430,2375 v1(3440,2365)
NetR56_1: R56.1 R244.2 U7.6 | length 635.2
  L1-TOP w10: R56.1@3249.88,1975 3249.88,2009.88 3315,2075 3385,2075 3455,2145 U7.6@3516.57,2145
  L6-BOT w10: R244.2@3249.88,1975 3249.88,2014.88 3310,2075 3385,2075 v1(3440,2130)
NetR59_1: R59.1 R251.2 U6.9 | length 375.3
  L1-TOP w10: U6.9@3520,618.43 v1(3520,695) 3525,695 3560,730 R59.1@3654.88,730
  L6-BOT w10: v1(3520,695) 3525,695 3560,730 R251.2@3654.88,730
NetR60_1: R60.1 R254.2 U7.13 | length 465.4
  L1-TOP w10: U7.13@3713.43,2345 3770,2345 v1(3790,2365) 3865,2365 3925.12,2425.12 R60.1@3925.12,2460
  L6-BOT w10: v1(3790,2365) 3820.12,2365 R254.2@3930.12,2475
NetR62_1: R62.1 U8.8 | length 136.4
  L1-TOP w10: U8.8@3801.85,1055 3805.12,1051.73 R62.1@3805.12,920
NetR64_1: R64.1 R72.2 U6.6 | length 625.2
  L1-TOP w10: U6.6@3515,416.57 U6.6@3520,421.57 3520,370 3550,340 3585,340 3625,380 R64.1@3654.88,380 3654.88,364.88 R64.1@3635,345 ; 3575,340 3595,320 3860,320 3874.88,334.88 R72.2@3874.88,380
  other v1: 3555,340
NetR65_2: R65.2 U9.5 | length 121.4
  L1-TOP w10: R65.2@3810,2969.88 3820.12,2969.88 3860,2930 U9.5@3860,2875.16
NetR66_2: R66.2 R75.1 U8.13 | length 463.8
  L1-TOP w10: U8.13@3801.85,1305 3885,1305 3910,1330 3935,1330 3955,1350 3955,1390.12 R75.1@4010,1445.12 ; R66.2@3915.12,1560 4010,1465.12 R75.1@4010,1445.12 ; R75.1@3990.12,1445.12 R75.1@4010,1445.12
NetR69_1: R69.1 R257.2 U7.9 | length 661.1
  L1-TOP w10: U7.9@3713.43,2145 3775,2145 v1(3790,2130) 3790,2115 3865,2040 3940,2040 3980.12,1999.88 R69.1@3980.12,1965
  L6-BOT w10: v1(3790,2130) 3790,2115 3865,2040 3945,2040 3980.12,2004.88 R257.2@3980.12,1965
NetR70_1: R70.1 R249.2 U8.9 | length 465.5
  L1-TOP w10: v1(3680.12,999.88) 3720,1039.76 3720,1075 3750,1105 3875,1105 3914.88,1065.12 R70.1@3914.88,1000
  L6-BOT w10: R249.2@3680.12,915 v1(3680.12,999.88)
NetR70_2: R70.2 R71.1 R80.1 R259.2 | length 587.7
  L1-TOP w10: v1(4080,765) 4065,780 R71.1@4015.12,780 4025.12,790 R70.2@4025.12,1000 4124.88,900.24 R80.1@4124.88,840
  L6-BOT w10: R259.2@3995.12,750 4065,750 v1(4080,765)
NetR73_2: R73.2 U9.1 | length 116.3
  L1-TOP w10: R73.2@4020,2974.88 4020,2970 4060,2930 U9.1@4060,2875.16
NetR74_1: R74.1 R79.2 U12.11 | length 872
  L1-TOP w10: R79.2@4235.12,1490 4235.12,1590 R74.1@4215.12,1610 4255,1610 4305,1660 4585,1660 4605,1640 4660,1640 4720,1580 4760,1580 4785,1605 4785,1645 4770,1660 U12.11@4770,1708.43
NetR74_2: R74.2 R88.1 R89.2 U12.13 U15.2 U15.6 | length 1825.6
  L1-TOP w10: R74.2@4104.88,1610 4104.88,1674.88 4133,1703 4353,1703 4429.88,1779.88 R89.2@4490,1779.88 ; R89.2@4499.88,1770 4320,1949.88 4320,2115.96 4344.04,2140 4460,2140 4495.12,2104.88 R88.1@4495.12,2085 4671.57,2085 U15.2@4676.57,2080 ; U12.13@4670,1708.43 4670,1745 4645,1770 4600,1770 4565,1735 4510,1735 4490,1755 4490,1790 4575,1875 4671.57,1875 U15.6@4676.57,1880
NetR77_1: R77.1 U10.12 | length 122.6
  L1-TOP w10: R77.1@4255.12,2550 4260,2550 4320,2610 U10.12@4320,2642.84
NetR78_2: R78.2 U10.7 | length 157.5
  L1-TOP w10: R78.2@4135,2974.88 4170.12,2974.88 4220,2925 U10.7@4220,2873.16
NetR82_1: R82.1 U10.1 | length 132.4
  L1-TOP w10: R82.1@4470,2984.88 4520,2934.88 U10.1@4520,2873.16
NetR83_1: R83.1 R84.2 U11.5 | length 324.1
  L1-TOP w10: R83.1@4250,1245 R84.2@4250,1135.24 4310.12,1135.24 4365,1190.12 U11.5@4441.57,1190.12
